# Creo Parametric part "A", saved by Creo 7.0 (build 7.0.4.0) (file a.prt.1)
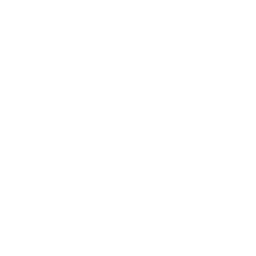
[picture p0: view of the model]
Materials in the file: S235JRG2

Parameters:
  PTC_MATERIAL_NAME = "S235JRG2"
  BENENNUNG = "XXX"
  DATUM = "XX.XX.XX"
  ERSTELLER = "ARINDA"
  TEILETYP = "Fertigungsteil"
  SELECT_EN_NAME = "S235JRG2"
  SELECT_DIN_NAME = "RSt37-2"
  SELECT_DIN_NUMBER = "1.0038"
  SELECT_ASTM_NAME = "A 283 M Grade 2"
  MATERIAL_GROUP = "ME_ST_Baustahl"
  STANDARD_EN_DELIVERYSPEC = "DIN EN 10025"
  STANDARD_DIN_DELIVERYSPEC = "DIN 17100"

Other parameters: MASSE

Created from: ARINDA-STARTTEIL.PRT

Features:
  1. coordinate system "CS0"
  2. datum plane "DTM1", "T_RECHTS_Y-Z"
  3. datum plane "DTM2", "T_OBEN_X-Z"
  4. datum plane "DTM3", "T_VORNE_X-Y"
  5. datum axis "T_X-ACHSE"
  6. datum axis "A_1"
  7. datum axis "A_2"

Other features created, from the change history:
  extrusion "Profil 1"

Other named items: T_BASIC, T_Y-ACHSE, T_Z-ACHSE

Layers: 00_STD-ACHSEN, 00_STD-EBENEN, 00_STD-KOORDSYS, VOLUMENGEOMETRIE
